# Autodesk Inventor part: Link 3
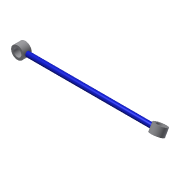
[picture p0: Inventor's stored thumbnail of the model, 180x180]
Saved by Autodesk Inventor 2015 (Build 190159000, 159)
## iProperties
Created: 2020-09
Part Number: Link 3
Material: 一般
Document SubType Name: Modeling
Designer: 徐冠倫
Mass: 0.863118 g
Surface Area: 12.5981 cm^2
Volume: 0.863118 cm^3
Density: 1 g/cm^3
Appearance: 預設
Author: IANNIAN
Title: D:\Desktop\OCW-Computer-Aided Engineering Drawing\OCW_Topic 06：組合圖與機構模擬(進階)\6-2_Inventor Studio\Banet\Banet(STP)\Part3.stp
Creation Date: 2020-09-04
Sending System: Autodesk Inventor 2020
Preprocessor: ST-DEVELOPER v18
Author: 徐冠倫
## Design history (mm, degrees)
node "Part31"
body "Solid1"
node "Base1"
